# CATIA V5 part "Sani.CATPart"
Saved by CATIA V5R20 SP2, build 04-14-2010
Part number: Part2
Bounding box of the stored display mesh (mm): x -33 to 33, y -27.548 to 27.548, z -1.995 to 6.995
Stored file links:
  C:\Documents and Settings\Administrator\My Documents\Hobi_dokumenti\CAD_CNC\Clap_CATIA\Sani.CATPart
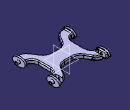
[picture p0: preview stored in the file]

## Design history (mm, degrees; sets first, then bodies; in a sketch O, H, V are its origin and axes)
Set1
  Point1: type Center, Curve edge [face of Mirror3 | face of Mirror3]
  Point2: type Center, Curve edge [face of Mirror2 | face of Mirror3]
  Point3: type Center, Curve edge [face of Mirror3 | face of Mirror3]
Body1 (main body)
  Sketch1 on xy-plane, origin (0, 0, 0), H (1, 0, 0), V (0, 1, 0)
    line L1 (-30, 25) -> (30, 25)
    line L2 (30, 25) -> (30, -25)
    line L3 (30, -25) -> (-30, -25)
    line L4 (-30, -25) -> (-30, 25)
    reference intersected line E2 through (0, 0) direction (0, 1) from yz-plane
    reference intersected line E3 through (0, 0) direction (-1, 0) from zx-plane
    distance E3 L3 = 25
    distance E3 L1 = 25
    distance E2 L2 = 30
    distance E2 L4 = 30
    horizontal: L1 H, L3 H, E3 H
    vertical: L2 V, L4 V, E2 V
    perpendicularity: E2 L1
  Pad1: profile Sketch1, direction (0, 0, 1), length 5
  Sketch2 on start face of Pad1, origin (0, 0, 0), H (1, 0, 0), V (0, -1, 0)
    offset line E1 (20, 25) -> (20, -25) from edge [start face of Pad1 | face of Pad1 from Sketch1.L2]
    offset line E2 (20, 7) -> (20, -7) from edge [start face of Pad1 | face of Pad1 from Sketch1.L2]
    point P1 (20, 25)
    point P2 (20, -25)
    offset line E3 (-20, -25) -> (-20, 25) from edge [start face of Pad1 | face of Pad1 from Sketch1.L4]
    offset line E4 (-20, -7) -> (-20, 7) from edge [start face of Pad1 | face of Pad1 from Sketch1.L4]
    point P3 (-20, -25)
    point P4 (-20, 25)
    offset line E5 (-30, 15) -> (30, 15) from edge [start face of Pad1 | face of Pad1 from Sketch1.L3]
    offset line E6 (-30, 15) -> (-28, 15) from edge [start face of Pad1 | face of Pad1 from Sketch1.L3]
    offset line E7 (28, 15) -> (30, 15) from edge [start face of Pad1 | face of Pad1 from Sketch1.L3]
    point P5 (-30, 15)
    point P6 (30, 15)
    offset line E8 (30, -15) -> (-30, -15) from edge [start face of Pad1 | face of Pad1 from Sketch1.L1]
    offset line E9 (-28, -15) -> (-30, -15) from edge [start face of Pad1 | face of Pad1 from Sketch1.L1]
    offset line E10 (30, -15) -> (28, -15) from edge [start face of Pad1 | face of Pad1 from Sketch1.L1]
    point P7 (30, -15)
    point P8 (-30, -15)
    arc A1 centre (-28, 7) radius 8 from (-28, 15) to (-20, 7) cw
    arc A2 centre (-28, -7) radius 8 from (-20, -7) to (-28, -15) cw
    arc A3 centre (28, 7) radius 8 from (28, 15) to (20, 7) ccw
    arc A4 centre (28, -7) radius 8 from (20, -7) to (28, -15) ccw
    line L1 (30, -15) -> (30, 15)
    line L2 (-30, -15) -> (-30, 15)
    radius A1 = 8
    radius A2 = 8
    radius A3 = 8
    radius A4 = 8
    coincidence: E5 P6, E3 P4, E3 P3, E8 P7, E5 P5, E1 P1, E1 P2, E8 P8
    tangency: A1 E5, A1 E3, A2 E3, A2 E8, A3 E5, A3 E1, A4 E1, A4 E8
    vertical: L1 V, L2 V
  Pocket1: profile Sketch2, direction (0, 0, 1), length 5
  Sketch3 on start face of Pad1, origin (0, 0, 0), H (1, 0, 0), V (0, -1, 0)
    offset line E1 (30, -8) -> (-30, -8) from edge [start face of Pad1 | face of Pad1 from Sketch1.L1]
    point P2 (-30, -8)
    line L1 (-20, -25) -> (-13.0718, -13)
    point P3 (-10.185, -8)
    point P4 (-20, -25)
    reference projected line E2 (-30, -25) -> (-30, 25) from edge [start face of Pad1 | face of Pad1 from Sketch1.L4]
    reference projected line E3 (30, -25) -> (-30, -25) from edge [start face of Pad1 | face of Pad1 from Sketch1.L1]
    reference projected line E4 (30, -25) -> (-30, -25) from edge [start face of Pad1 | face of Pad1 from Sketch1.L1]
    arc A1 centre (-4.4115, -18) radius 10 from (-4.4115, -8) to (-13.0718, -13) ccw
    point P5 (-4.4115, -8)
    point P6 (-13.0718, -13)
    point P8 (10.185, -8)
    point P9 (20, -25)
    point P10 (13.0718, -13)
    point P12 (4.4115, -8)
    line L2 (20, -25) -> (13.0718, -13)
    arc A2 centre (4.4115, -18) radius 10 from (4.4115, -8) to (13.0718, -13) cw
    line L3 (-20, -25) -> (20, -25)
    line L4 (-4.4115, -8) -> (4.4115, -8)
    point P13 (-10.185, 8)
    point P14 (-20, 25)
    point P15 (-4.4115, 8)
    point P16 (-13.0718, 13)
    point P18 (10.185, 8)
    point P19 (20, 25)
    point P20 (13.0718, 13)
    point P22 (4.4115, 8)
    line L5 (-20, 25) -> (-13.0718, 13)
    arc A3 centre (-4.4115, 18) radius 10 from (-4.4115, 8) to (-13.0718, 13) cw
    line L6 (20, 25) -> (13.0718, 13)
    arc A4 centre (4.4115, 18) radius 10 from (4.4115, 8) to (13.0718, 13) ccw
    line L7 (-20, 25) -> (20, 25)
    line L8 (-4.4115, 8) -> (4.4115, 8)
    distance E2 P4 = 10
    distance P4 E3 = 0
    angle E4 L1 = 60
    radius A1 = 10
    coincidence: P3 E1, E1 P2, L1 P3
    tangency: A1 E1, A1 L1, L4 A1
    symmetry: P3 P8 V, P4 P9 V, P6 P10 V, P5 P12 V, L1 L2 V, A1 A2 V, P3 P13 H, P4 P14 H, P5 P15 H, P6 P16 H, P8 P18 H, P9 P19 H, P10 P20 H, P12 P22 H, L1 L5 H, A1 A3 H, L2 L6 H, A2 A4 H, L3 L7 H, L4 L8 H
    horizontal: L3 H
  Pocket2: profile Sketch3, direction (0, 0, 1), length 5
  Fillet1: radius 10, on edge [face of Pocket2 from Sketch3.L5 | face of Pad1 from Sketch1.L3]; edge [face of Pad1 from Sketch1.L1 | face of Pocket2 from Sketch3.L1]; edge [face of Pad1 from Sketch1.L3 | face of Pocket2 from Sketch3.L6]; edge [face of Pocket2 from Sketch3.L2 | face of Pad1 from Sketch1.L1]
  Sketch4 on face of Pad1 from Sketch1.L4, origin (-30, 0, 0), H (0, -1, 0), V (0, 0, 1)
    circle A1 centre (-20, 2.5) radius 2
    point P1 (-20, 2.5)
    radius A1 = 2
    distance H P1 = 2.5
    distance V P1 = 20
  Pad2: profile Sketch4, direction (-1, 0, 0), length 3
  Mirror1: of Pad2, Sketch4, about yz-plane
  Mirror2: of Pad2, Sketch4, about zx-plane
  Mirror3: of the body so far, about yz-plane
  Sketch5 on face of Mirror3, origin (-33, 20, 2.5), H (0, 1, 0), V (0, 0, -1)
    point P1 (0, 0)
  Hole1: placed by Sketch5, at (-33, 20, 2.5) direction (1, 0, 0), diameter 2.4, through (limit type 6), threaded, thread diameter 3, thread depth 10, pitch 0.5
  Mirror4: of Hole1, about zx-plane
  Mirror5: of Hole1, about yz-plane
  Sketch6 on face of Mirror3, origin (33, -20, 2.5), H (0, 1, 0), V (0, 0, 1)
    point P1 (0, 0)
  Hole2: placed by Sketch6, at (33, -20, 2.5) direction (-1, 0, 0), diameter 2.4, through (limit type 6), threaded, thread diameter 3, thread depth 10, pitch 0.5
  Chamfer1: length 1, angle 45, on edge [face of Mirror3 | face of Mirror3] (x12)
  Sketch7 on face of Mirror3, origin (30, 0, 0), H (0, 1, 0), V (0, 0, 1)
    circle A1 centre (20, 2.5) radius 2
    point P1 (20, 2.5)
    ellipse A2 centre (20, 2.5) semi-axes 7.5477, 4.6108 rotation 0
    radius A1 = 2
    distance P1 H = 2.5
    distance P1 V = 20
    "Radius" A2 = 7.5477
    "Radius" A2 = 4.6108
  Pad3: profile Sketch7, direction (-1, 0, 0), length 2
  Mirror6: of Pad3, Sketch7, about zx-plane
  Mirror7: of Pad3, Sketch7, about yz-plane
  Mirror8: of the body so far, about yz-plane
  Fillet2: radius 1.1, on edge [face of Mirror8 | face of Mirror8] (x24); edge [face of Mirror6 | face of Mirror8] (x3); edge [face of Mirror8 | face of Mirror6] (x5)
  Sketch8 on face of Mirror8, origin (0, 0, 5), H (1, 0, 0), V (0, 1, 0)
    point P1 (-26.8, 26.2)
    line L1 (-26.8, 26.2) -> (-23, 26.2)
    line L2 (-23, 26.2) -> (-23, 16.2)
    line L3 (-23, 16.2) -> (-26.8, 16.2)
    line L4 (-26.8, 16.2) -> (-26.8, 26.2)
    point P2 (-23, 26.2)
    point P3 (-23, 16.2)
    point P4 (-26.8, 16.2)
    point P5 (26.8, 26.2)
    point P6 (23, 26.2)
    point P7 (23, 16.2)
    point P8 (26.8, 16.2)
    line L5 (26.8, 26.2) -> (23, 26.2)
    line L6 (23, 26.2) -> (23, 16.2)
    line L7 (23, 16.2) -> (26.8, 16.2)
    line L8 (26.8, 16.2) -> (26.8, 26.2)
    length L1 = 3.8
    length L2 = 10
    distance H L3 = 16.2
    distance V L2 = 23
    horizontal: L1 H, L3 H
    vertical: L2 V, L4 V
    symmetry: P1 P5 V, P2 P6 V, P3 P7 V, P4 P8 V, L1 L5 V, L2 L6 V, L3 L7 V, L4 L8 V
  Pocket3: profile Sketch8, direction (0, 0, -1), length 6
